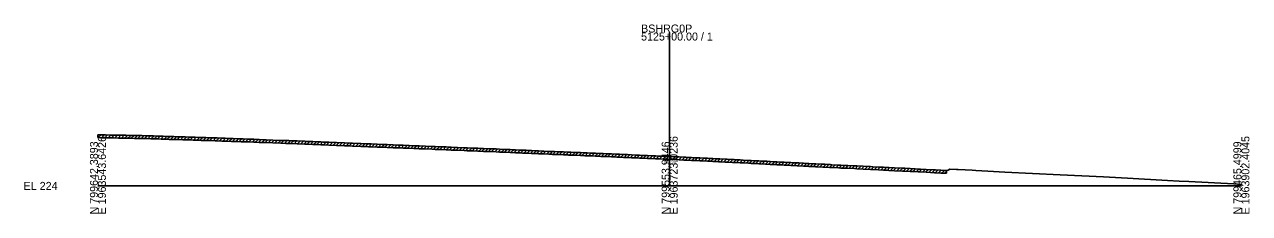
# Model space of a CAD drawing. Extents: x -26 to 1986619, y -10 to 827846.
# Drawn here: x 974.3 to 1402.8, y -9.7 to 56.6 of the extents above; entities that cross this region are included whole.
import ezdxf

# ---------------------------------------------------------------- set-up
doc = ezdxf.new("R2010")
doc.units = 0
for name, color, linetype in [('Default', 7, 'Continuous'), ('RD_GPK_XS_Cell', 7, 'Continuous'), ('RD_XS_ExGround', 7, 'Continuous'), ('RD_XS_ExPaveRet', 7, 'Continuous'), ('RD_XS_TX_Elev_EX', 7, 'Continuous')]:
    doc.layers.add(name, color=color, linetype=linetype)

msp = doc.modelspace()

# ---------------------------------------------------------------- linework, layer by layer
at = {"layer": 'RD_GPK_XS_Cell'}
for p, q in [((1200, 0), (1200, 53.78)), ((1000, 0), (1200, 0)), ((1200, 0), (1400, 0))]:
    msp.add_line(p, q, dxfattribs=at)
at = {"layer": 'RD_XS_ExGround'}
msp.add_lwpolyline([(1000, 17.93), (1000.41, 17.92), (1001.51, 17.89), (1002.28, 17.88), (1002.66, 17.87), (1004.14, 17.84), (1005.44, 17.82), (1007.17, 17.79), (1007.88, 17.77), (1008.23, 17.77), (1009.74, 17.74), (1011.03, 17.71), (1011.61, 17.7), (1012.77, 17.68), (1013.81, 17.65), (1015.34, 17.62), (1016.59, 17.59), (1017.22, 17.57), (1018.49, 17.53), (1019.38, 17.51), (1020.94, 17.46), (1022.17, 17.42), (1022.8, 17.4), (1024.09, 17.36), (1024.96, 17.33), (1026.55, 17.28), (1027.75, 17.25), (1028.41, 17.23), (1029.75, 17.18), (1030.53, 17.16), (1032.14, 17.11), (1033.31, 17.07), (1034, 17.05), (1035.42, 17), (1036.1, 16.98), (1037.74, 16.93), (1038.89, 16.89), (1039.61, 16.87), (1041.05, 16.83), (1041.68, 16.81), (1043.34, 16.74), (1044.47, 16.71), (1045.21, 16.68), (1046.7, 16.63), (1047.26, 16.61), (1048.95, 16.54), (1050.05, 16.51), (1050.82, 16.48), (1052.39, 16.42), (1052.84, 16.41), (1054.55, 16.34), (1055.62, 16.3), (1056.41, 16.27), (1057.99, 16.21), (1058.41, 16.19), (1058.81, 16.18), (1061.19, 16.08), (1063.97, 15.97), (1065.75, 15.91), (1066.77, 15.87), (1067.62, 15.84), (1069.75, 15.76), (1072.34, 15.65), (1073.2, 15.61), (1075.13, 15.54), (1076.95, 15.47), (1077.92, 15.43), (1078.81, 15.39), (1080.82, 15.31), (1083.5, 15.2), (1086.3, 15.1), (1088.15, 15.02), (1089.07, 14.98), (1091.96, 14.87), (1093.76, 14.79), (1094.65, 14.76), (1095.63, 14.72), (1097.63, 14.64), (1099.36, 14.57), (1100.22, 14.53), (1101.22, 14.49), (1103.29, 14.41), (1104.96, 14.34), (1105.8, 14.3), (1106.82, 14.26), (1108.92, 14.18), (1110.56, 14.11), (1111.37, 14.08), (1112.42, 14.03), (1114.56, 13.95), (1116.94, 13.85), (1118.02, 13.8), (1119.88, 13.73), (1120.2, 13.72), (1121.76, 13.65), (1122.52, 13.62), (1123.62, 13.57), (1125.48, 13.5), (1125.82, 13.49), (1128.09, 13.39), (1129.21, 13.35), (1131.07, 13.28), (1131.46, 13.26), (1132.95, 13.2), (1133.67, 13.17), (1134.82, 13.12), (1136.69, 13.05), (1137.16, 13.03), (1139.25, 12.95), (1140.42, 12.89), (1142.29, 12.8), (1142.82, 12.78), (1144.16, 12.73), (1144.82, 12.69), (1146.02, 12.64), (1147.6, 12.57), (1148.47, 12.53), (1149.76, 12.48), (1150.39, 12.45), (1151.62, 12.39), (1153.18, 12.32), (1153.49, 12.31), (1154.13, 12.28), (1155.36, 12.23), (1155.97, 12.2), (1157.76, 12.12), (1158.76, 12.08), (1159.09, 12.06), (1159.77, 12.03), (1160.96, 11.99), (1161.54, 11.96), (1162.83, 11.91), (1164.34, 11.85), (1164.69, 11.83), (1165.43, 11.8), (1166.56, 11.75), (1167.11, 11.73), (1168.76, 11.66), (1169.91, 11.61), (1170.29, 11.59), (1171.09, 11.56), (1172.16, 11.52), (1172.69, 11.5), (1174.04, 11.44), (1175.49, 11.38), (1175.9, 11.36), (1176.76, 11.32), (1177.77, 11.29), (1178.28, 11.27), (1179.64, 11.2), (1181.06, 11.14), (1181.51, 11.12), (1182.43, 11.08), (1183.37, 11.04), (1183.84, 11.02), (1185.24, 10.96), (1186.63, 10.89), (1188.07, 10.83), (1188.97, 10.79), (1189.42, 10.77), (1190.75, 10.71), (1192.21, 10.65), (1193.7, 10.58), (1194.99, 10.52), (1196.26, 10.47), (1197.77, 10.4), (1199.32, 10.33), (1200, 10.3), (1200.56, 10.27), (1201.78, 10.22), (1203.36, 10.14), (1204.96, 10.07), (1205.68, 10.04), (1206.14, 10.01), (1207.62, 9.95), (1208.93, 9.89), (1209.49, 9.86), (1210.6, 9.8), (1211.71, 9.75), (1213.22, 9.69), (1214.51, 9.62), (1215.11, 9.59), (1216.34, 9.53), (1217.09, 9.49), (1217.52, 9.47), (1219.42, 9.38), (1220.07, 9.35), (1221.97, 9.25), (1222.56, 9.22), (1223.02, 9.2), (1224.72, 9.11), (1225.66, 9.06), (1227.59, 8.95), (1228.03, 8.93), (1228.51, 8.9), (1229.99, 8.82), (1231.24, 8.76), (1231.9, 8.73), (1233.49, 8.65), (1233.99, 8.63), (1235.21, 8.55), (1236.79, 8.48), (1237.49, 8.45), (1238.9, 8.38), (1239.46, 8.35), (1240.03, 8.32), (1241.85, 8.22), (1242.38, 8.18), (1243.11, 8.15), (1244.6, 8.09), (1245.15, 8.06), (1246.84, 7.97), (1247.94, 7.91), (1248.71, 7.86), (1250.28, 7.79), (1250.74, 7.76), (1251.19, 7.74), (1253.53, 7.61), (1254.32, 7.57), (1255.92, 7.48), (1256.32, 7.46), (1256.74, 7.44), (1259.1, 7.31), (1259.89, 7.26), (1261.49, 7.2), (1261.9, 7.19), (1262.29, 7.17), (1264.68, 7.05), (1265.51, 7.01), (1267.71, 6.89), (1270.26, 6.76), (1271.12, 6.71), (1273.03, 6.59), (1274.85, 6.53), (1275.82, 6.47), (1276.72, 6.43), (1278.68, 6.33), (1281.4, 6.21), (1282.29, 6.17), (1284.19, 6.08), (1285.93, 6), (1286.97, 5.93), (1287.78, 5.89), (1289.75, 5.79), (1292.64, 5.62), (1292.95, 5.6), (1294.89, 5.5), (1295.91, 5.44), (1296.47, 5.46), (1297.48, 5.47), (1298.02, 5.89), (1300.3, 5.77), (1300.87, 5.74), (1305.77, 5.48), (1307.1, 5.4), (1311.35, 5.17), (1317.29, 4.87), (1336.57, 3.92), (1351.79, 3.16), (1360.16, 2.72), (1374.12, 1.95), (1378.27, 1.7), (1381.62, 1.53), (1397.37, 0.7), (1400, 0.53)], dxfattribs=at)
at = {"layer": 'RD_XS_ExPaveRet'}
for p, q in [((1000, 16.93), (1000, 17.93)), ((1000.1, 16.92), (1001.08, 17.9)), ((1001.25, 16.9), (1002.23, 17.88)), ((1002.41, 16.88), (1003.39, 17.86)), ((1003.56, 16.86), (1004.54, 17.84)), ((1004.72, 16.83), (1005.7, 17.82)), ((1005.88, 16.81), (1006.86, 17.79)), ((1007.03, 16.79), (1008.01, 17.77)), ((1008.19, 16.77), (1009.17, 17.75)), ((1009.34, 16.75), (1010.33, 17.73)), ((1010.5, 16.72), (1011.48, 17.71)), ((1011.66, 16.7), (1012.63, 17.68)), ((1012.81, 16.67), (1013.79, 17.65)), ((1013.96, 16.65), (1014.94, 17.63)), ((1015.11, 16.63), (1016.09, 17.6)), ((1016.26, 16.6), (1017.24, 17.57)), ((1017.41, 16.56), (1018.38, 17.54)), ((1018.55, 16.53), (1019.52, 17.5)), ((1019.7, 16.5), (1020.66, 17.46)), ((1020.84, 16.46), (1021.81, 17.43)), ((1021.98, 16.42), (1022.95, 17.39)), ((1023.12, 16.39), (1024.09, 17.36)), ((1024.27, 16.35), (1025.24, 17.32)), ((1025.41, 16.32), (1026.38, 17.29)), ((1026.55, 16.28), (1027.52, 17.25)), ((1027.69, 16.25), (1028.66, 17.22)), ((1028.84, 16.21), (1029.81, 17.18)), ((1029.98, 16.18), (1030.95, 17.15)), ((1031.12, 16.14), (1032.09, 17.11)), ((1032.27, 16.11), (1033.23, 17.07)), ((1033.4, 16.07), (1034.37, 17.04)), ((1034.55, 16.03), (1035.51, 17)), ((1035.69, 15.99), (1036.66, 16.96)), ((1036.83, 15.96), (1037.8, 16.92)), ((1037.97, 15.92), (1038.94, 16.89)), ((1039.11, 15.89), (1040.08, 16.86)), ((1040.26, 15.85), (1041.23, 16.82)), ((1041.4, 15.81), (1042.36, 16.78)), ((1042.53, 15.77), (1043.5, 16.74)), ((1043.67, 15.73), (1044.64, 16.7)), ((1044.81, 15.7), (1045.78, 16.66)), ((1045.95, 15.66), (1046.92, 16.62)), ((1047.09, 15.62), (1048.05, 16.58)), ((1048.22, 15.57), (1049.19, 16.54)), ((1049.36, 15.53), (1050.33, 16.5)), ((1050.5, 15.49), (1051.46, 16.46)), ((1051.64, 15.45), (1052.6, 16.42)), ((1052.77, 15.41), (1053.73, 16.37)), ((1053.91, 15.36), (1054.87, 16.33)), ((1055.04, 15.32), (1056, 16.28)), ((1056.18, 15.28), (1057.14, 16.24)), ((1057.31, 15.23), (1058.27, 16.2)), ((1058.45, 15.19), (1059.41, 16.15)), ((1059.58, 15.15), (1060.54, 16.11)), ((1060.71, 15.1), (1061.67, 16.06)), ((1061.84, 15.06), (1062.81, 16.02)), ((1062.98, 15.01), (1063.94, 15.98)), ((1064.11, 14.97), (1065.08, 15.93)), ((1065.25, 14.92), (1066.21, 15.89)), ((1066.38, 14.88), (1067.35, 15.85)), ((1067.52, 14.84), (1068.48, 15.8)), ((1068.65, 14.8), (1069.62, 15.76)), ((1069.79, 14.75), (1070.75, 15.71)), ((1070.92, 14.71), (1071.88, 15.67)), ((1072.05, 14.66), (1073.01, 15.62)), ((1073.18, 14.62), (1074.15, 15.58)), ((1074.32, 14.57), (1075.28, 15.54)), ((1075.45, 14.53), (1076.41, 15.49)), ((1076.58, 14.48), (1077.54, 15.44)), ((1077.72, 14.44), (1078.68, 15.4)), ((1078.85, 14.39), (1079.81, 15.35)), ((1079.98, 14.35), (1080.94, 15.31)), ((1081.12, 14.3), (1082.08, 15.26)), ((1082.25, 14.26), (1083.21, 15.22)), ((1083.38, 14.21), (1084.34, 15.17)), ((1084.51, 14.16), (1085.48, 15.13)), ((1085.65, 14.12), (1086.61, 15.08)), ((1086.78, 14.08), (1087.74, 15.04)), ((1087.91, 14.03), (1088.87, 14.99)), ((1089.04, 13.98), (1090, 14.94)), ((1090.18, 13.94), (1091.14, 14.9)), ((1091.31, 13.89), (1092.27, 14.85)), ((1092.44, 13.85), (1093.4, 14.81)), ((1093.57, 13.8), (1094.53, 14.76)), ((1094.71, 13.76), (1095.67, 14.72)), ((1095.84, 13.71), (1096.8, 14.67)), ((1096.97, 13.67), (1097.94, 14.63)), ((1098.11, 13.62), (1099.06, 14.58)), ((1099.24, 13.57), (1100.2, 14.53)), ((1100.37, 13.53), (1101.33, 14.48)), ((1101.5, 13.48), (1102.46, 14.44)), ((1102.63, 13.44), (1103.59, 14.4)), ((1103.76, 13.39), (1104.72, 14.35)), ((1104.89, 13.34), (1105.85, 14.3)), ((1106.02, 13.29), (1106.98, 14.25)), ((1107.16, 13.25), (1108.12, 14.21)), ((1108.29, 13.2), (1109.25, 14.16)), ((1109.42, 13.16), (1110.38, 14.12)), ((1110.55, 13.11), (1111.51, 14.07)), ((1111.68, 13.06), (1112.64, 14.02)), ((1112.81, 13.01), (1113.78, 13.98)), ((1113.95, 12.97), (1114.91, 13.93)), ((1115.08, 12.93), (1116.04, 13.89)), ((1116.21, 12.88), (1117.17, 13.84)), ((1117.34, 12.83), (1118.3, 13.79)), ((1118.47, 12.78), (1119.44, 13.75)), ((1119.61, 12.74), (1120.57, 13.7)), ((1120.74, 12.69), (1121.7, 13.65)), ((1121.87, 12.65), (1122.83, 13.61)), ((1123, 12.6), (1123.96, 13.56)), ((1124.13, 12.55), (1125.1, 13.52)), ((1125.27, 12.51), (1126.23, 13.47)), ((1126.4, 12.47), (1127.36, 13.42)), ((1127.53, 12.42), (1128.49, 13.38)), ((1128.66, 12.37), (1129.62, 13.33)), ((1129.79, 12.32), (1130.76, 13.29)), ((1130.93, 12.28), (1131.89, 13.24)), ((1132.06, 12.24), (1133.02, 13.2)), ((1133.2, 12.19), (1134.15, 13.15)), ((1134.32, 12.14), (1135.29, 13.1)), ((1135.46, 12.1), (1136.42, 13.06)), ((1136.59, 12.05), (1137.56, 13.02)), ((1137.73, 12.01), (1138.69, 12.97)), ((1138.86, 11.97), (1139.82, 12.92)), ((1139.99, 11.91), (1140.94, 12.87)), ((1141.11, 11.86), (1142.06, 12.81)), ((1142.23, 11.8), (1143.19, 12.76)), ((1143.36, 11.76), (1144.32, 12.72)), ((1144.49, 11.71), (1145.45, 12.67)), ((1145.62, 11.66), (1146.58, 12.61)), ((1146.75, 11.61), (1147.7, 12.56)), ((1147.87, 11.55), (1148.83, 12.51)), ((1149, 11.51), (1149.96, 12.47)), ((1150.13, 11.46), (1151.09, 12.42)), ((1151.26, 11.41), (1152.22, 12.37)), ((1152.39, 11.36), (1153.34, 12.31)), ((1153.51, 11.31), (1154.47, 12.26)), ((1154.64, 11.26), (1155.6, 12.22)), ((1155.77, 11.21), (1156.73, 12.17)), ((1156.9, 11.16), (1157.86, 12.12)), ((1158.03, 11.11), (1158.99, 12.07)), ((1159.16, 11.06), (1160.12, 12.02)), ((1160.29, 11.01), (1161.25, 11.97)), ((1161.42, 10.97), (1162.38, 11.93)), ((1162.55, 10.92), (1163.51, 11.88)), ((1163.68, 10.87), (1164.64, 11.83)), ((1164.82, 10.83), (1165.77, 11.78)), ((1165.94, 10.78), (1166.9, 11.74)), ((1167.07, 10.73), (1168.03, 11.69)), ((1168.2, 10.68), (1169.16, 11.64)), ((1169.33, 10.63), (1170.29, 11.59)), ((1170.46, 10.58), (1171.43, 11.55)), ((1171.6, 10.54), (1172.56, 11.5)), ((1172.73, 10.5), (1173.69, 11.45)), ((1173.86, 10.45), (1174.82, 11.4)), ((1174.99, 10.4), (1175.95, 11.35)), ((1176.12, 10.35), (1177.08, 11.31)), ((1177.25, 10.31), (1178.22, 11.27)), ((1178.39, 10.26), (1179.34, 11.22)), ((1179.51, 10.21), (1180.47, 11.16)), ((1180.64, 10.16), (1181.59, 11.11)), ((1181.76, 10.1), (1182.73, 11.06)), ((1182.9, 10.06), (1183.86, 11.02)), ((1184.03, 10.01), (1184.99, 10.97)), ((1185.16, 9.96), (1186.11, 10.92)), ((1186.28, 9.91), (1187.24, 10.87)), ((1187.41, 9.86), (1188.37, 10.82)), ((1188.54, 9.81), (1189.5, 10.77)), ((1189.67, 9.76), (1190.62, 10.72)), ((1190.79, 9.71), (1191.75, 10.67)), ((1191.92, 9.66), (1192.88, 10.62)), ((1193.05, 9.61), (1194.01, 10.57)), ((1194.18, 9.56), (1195.14, 10.52)), ((1195.31, 9.51), (1196.26, 10.47)), ((1196.43, 9.46), (1197.39, 10.42)), ((1197.56, 9.41), (1198.52, 10.37)), ((1198.69, 9.36), (1199.64, 10.31)), ((1199.81, 9.31), (1200.77, 10.26)), ((1200.94, 9.25), (1201.9, 10.21)), ((1202.07, 9.2), (1203.02, 10.16)), ((1203.19, 9.15), (1204.15, 10.11)), ((1204.32, 9.1), (1205.28, 10.05)), ((1205.45, 9.05), (1206.4, 10)), ((1206.57, 9), (1207.53, 9.95)), ((1207.7, 8.95), (1208.66, 9.9)), ((1208.83, 8.89), (1209.78, 9.85)), ((1209.95, 8.84), (1210.9, 9.79)), ((1211.07, 8.78), (1212.03, 9.74)), ((1212.2, 8.73), (1213.16, 9.69)), ((1213.33, 8.68), (1214.28, 9.63)), ((1214.45, 8.63), (1215.4, 9.58)), ((1215.57, 8.57), (1216.52, 9.52)), ((1216.69, 8.51), (1217.64, 9.46)), ((1217.81, 8.45), (1218.77, 9.41)), ((1218.94, 8.4), (1219.89, 9.35)), ((1220.06, 8.35), (1221.01, 9.3)), ((1221.18, 8.29), (1222.13, 9.24)), ((1222.3, 8.23), (1223.25, 9.18)), ((1223.42, 8.17), (1224.37, 9.12)), ((1224.54, 8.12), (1225.49, 9.07)), ((1225.66, 8.06), (1226.61, 9.01)), ((1226.78, 8), (1227.73, 8.94)), ((1227.89, 7.93), (1228.84, 8.88)), ((1229.01, 7.87), (1229.96, 8.82)), ((1230.13, 7.81), (1231.08, 8.77)), ((1231.25, 7.76), (1232.21, 8.71)), ((1232.38, 7.7), (1233.33, 8.66)), ((1233.5, 7.65), (1234.45, 8.6)), ((1234.62, 7.59), (1235.56, 8.54)), ((1235.73, 7.53), (1236.69, 8.48)), ((1236.86, 7.48), (1237.81, 8.43)), ((1237.98, 7.42), (1238.94, 8.38)), ((1239.11, 7.37), (1240.06, 8.32)), ((1240.23, 7.31), (1241.17, 8.25)), ((1241.34, 7.25), (1242.29, 8.19)), ((1242.45, 7.18), (1243.41, 8.13)), ((1243.58, 7.13), (1244.54, 8.09)), ((1244.71, 7.08), (1245.66, 8.03)), ((1245.83, 7.02), (1246.78, 7.97)), ((1246.95, 6.96), (1247.9, 7.91)), ((1248.06, 6.9), (1249.01, 7.85)), ((1249.18, 6.84), (1250.14, 7.79)), ((1250.31, 6.79), (1251.26, 7.74)), ((1251.42, 6.73), (1252.37, 7.67)), ((1252.54, 6.66), (1253.49, 7.61)), ((1253.66, 6.6), (1254.61, 7.55)), ((1254.78, 6.54), (1255.73, 7.49)), ((1255.9, 6.49), (1256.84, 7.43)), ((1257.01, 6.42), (1257.96, 7.37)), ((1258.13, 6.36), (1259.07, 7.31)), ((1259.24, 6.3), (1260.19, 7.25)), ((1260.37, 6.24), (1261.33, 7.21)), ((1261.5, 6.2), (1262.46, 7.16)), ((1262.63, 6.15), (1263.58, 7.11)), ((1263.75, 6.1), (1264.71, 7.05)), ((1264.88, 6.04), (1265.83, 6.99)), ((1266, 5.98), (1266.95, 6.93)), ((1267.12, 5.92), (1268.06, 6.87)), ((1268.23, 5.86), (1269.18, 6.81)), ((1269.35, 5.81), (1270.3, 6.76)), ((1270.47, 5.75), (1271.42, 6.69)), ((1271.58, 5.68), (1272.53, 6.62)), ((1272.7, 5.61), (1273.65, 6.57)), ((1273.82, 5.56), (1274.79, 6.53)), ((1274.96, 5.52), (1275.91, 6.47)), ((1276.08, 5.46), (1277.03, 6.41)), ((1277.2, 5.41), (1278.15, 6.36)), ((1278.32, 5.35), (1279.28, 6.31)), ((1279.45, 5.3), (1280.4, 6.25)), ((1280.57, 5.25), (1281.53, 6.2)), ((1281.7, 5.2), (1282.66, 6.15)), ((1282.83, 5.14), (1283.78, 6.1)), ((1283.95, 5.09), (1284.91, 6.04)), ((1285.08, 5.04), (1286.03, 5.99)), ((1286.2, 4.98), (1287.14, 5.92)), ((1287.31, 4.91), (1288.26, 5.86)), ((1288.43, 4.86), (1289.38, 5.81)), ((1289.55, 4.8), (1290.5, 5.74)), ((1290.66, 4.73), (1291.61, 5.68)), ((1291.78, 4.67), (1292.72, 5.62)), ((1292.89, 4.61), (1293.84, 5.55)), ((1294.01, 4.54), (1294.96, 5.49)), ((1295.12, 4.48), (1296.09, 5.44)), ((1296.27, 4.45), (1296.82, 5)), ((1296.82, 4.47), (1296.82, 5.47))]:
    msp.add_line(p, q, dxfattribs=at)
msp.add_lwpolyline([(1000, 16.93), (1000.41, 16.92), (1001.51, 16.89), (1002.28, 16.88), (1002.66, 16.87), (1004.14, 16.84), (1005.44, 16.82), (1007.17, 16.79), (1007.88, 16.77), (1008.23, 16.77), (1009.74, 16.74), (1011.03, 16.71), (1011.61, 16.7), (1012.77, 16.68), (1013.81, 16.65), (1015.34, 16.62), (1016.59, 16.59), (1017.22, 16.57), (1018.49, 16.53), (1019.38, 16.51), (1020.94, 16.46), (1022.17, 16.42), (1022.8, 16.4), (1024.09, 16.36), (1024.96, 16.33), (1026.55, 16.28), (1027.75, 16.25), (1028.41, 16.23), (1029.75, 16.18), (1030.53, 16.16), (1032.14, 16.11), (1033.31, 16.07), (1034, 16.05), (1035.42, 16), (1036.1, 15.98), (1037.74, 15.93), (1038.89, 15.89), (1039.61, 15.87), (1041.05, 15.83), (1041.68, 15.81), (1043.34, 15.74), (1044.47, 15.71), (1045.21, 15.68), (1046.7, 15.63), (1047.26, 15.61), (1048.95, 15.54), (1050.05, 15.51), (1050.82, 15.48), (1052.39, 15.42), (1052.84, 15.41), (1054.55, 15.34), (1055.62, 15.3), (1056.41, 15.27), (1057.99, 15.21), (1058.41, 15.19), (1058.81, 15.18), (1061.19, 15.08), (1063.97, 14.97), (1065.75, 14.91), (1066.77, 14.87), (1067.62, 14.84), (1069.75, 14.76), (1072.34, 14.65), (1073.2, 14.61), (1075.13, 14.54), (1076.95, 14.47), (1077.92, 14.43), (1078.81, 14.39), (1080.82, 14.31), (1083.5, 14.2), (1086.3, 14.1), (1088.15, 14.02), (1089.07, 13.98), (1091.96, 13.87), (1093.76, 13.79), (1094.65, 13.76), (1095.63, 13.72), (1097.63, 13.64), (1099.36, 13.57), (1100.22, 13.53), (1101.22, 13.49), (1103.29, 13.41), (1104.96, 13.34), (1105.8, 13.3), (1106.82, 13.26), (1108.92, 13.18), (1110.56, 13.11), (1111.37, 13.08), (1112.42, 13.03), (1114.56, 12.95), (1116.94, 12.85), (1118.02, 12.8), (1119.88, 12.73), (1120.2, 12.72), (1121.76, 12.65), (1122.52, 12.62), (1123.62, 12.57), (1125.48, 12.5), (1125.82, 12.49), (1128.09, 12.39), (1129.21, 12.35), (1131.07, 12.28), (1131.46, 12.26), (1132.95, 12.2), (1133.67, 12.17), (1134.82, 12.12), (1136.69, 12.05), (1137.16, 12.03), (1139.25, 11.95), (1140.42, 11.89), (1142.29, 11.8), (1142.82, 11.78), (1144.16, 11.73), (1144.82, 11.69), (1146.02, 11.64), (1147.6, 11.57), (1148.47, 11.53), (1149.76, 11.48), (1150.39, 11.45), (1151.62, 11.39), (1153.18, 11.32), (1153.49, 11.31), (1154.13, 11.28), (1155.36, 11.23), (1155.97, 11.2), (1157.76, 11.12), (1158.76, 11.08), (1159.09, 11.06), (1159.77, 11.03), (1160.96, 10.99), (1161.54, 10.96), (1162.83, 10.91), (1164.34, 10.85), (1164.69, 10.83), (1165.43, 10.8), (1166.56, 10.75), (1167.11, 10.73), (1168.76, 10.66), (1169.91, 10.61), (1170.29, 10.59), (1171.09, 10.56), (1172.16, 10.52), (1172.69, 10.5), (1174.04, 10.44), (1175.49, 10.38), (1175.9, 10.36), (1176.76, 10.32), (1177.77, 10.29), (1178.28, 10.27), (1179.64, 10.2), (1181.06, 10.14), (1181.51, 10.12), (1182.43, 10.08), (1183.37, 10.04), (1183.84, 10.02), (1185.24, 9.96), (1186.63, 9.89), (1188.07, 9.83), (1188.97, 9.79), (1189.42, 9.77), (1190.75, 9.71), (1192.21, 9.65), (1193.7, 9.58), (1194.99, 9.52), (1196.26, 9.47), (1197.77, 9.4), (1199.32, 9.33), (1200, 9.3), (1200.56, 9.27), (1201.78, 9.22), (1203.36, 9.14), (1204.96, 9.07), (1205.68, 9.04), (1206.14, 9.01), (1207.62, 8.95), (1208.93, 8.89), (1209.49, 8.86), (1210.6, 8.8), (1211.71, 8.75), (1213.22, 8.69), (1214.51, 8.62), (1215.11, 8.59), (1216.34, 8.53), (1217.09, 8.49), (1217.52, 8.47), (1219.42, 8.38), (1220.07, 8.35), (1221.97, 8.25), (1222.56, 8.22), (1223.02, 8.2), (1224.72, 8.11), (1225.66, 8.06), (1227.59, 7.95), (1228.03, 7.93), (1228.51, 7.9), (1229.99, 7.82), (1231.24, 7.76), (1231.9, 7.73), (1233.49, 7.65), (1233.99, 7.63), (1235.21, 7.55), (1236.79, 7.48), (1237.49, 7.45), (1238.9, 7.38), (1239.46, 7.35), (1240.03, 7.32), (1241.85, 7.22), (1242.38, 7.18), (1243.11, 7.15), (1244.6, 7.09), (1245.15, 7.06), (1246.84, 6.97), (1247.94, 6.91), (1248.71, 6.86), (1250.28, 6.79), (1250.74, 6.76), (1251.19, 6.74), (1253.53, 6.61), (1254.32, 6.57), (1255.92, 6.48), (1256.32, 6.46), (1256.74, 6.44), (1259.1, 6.31), (1259.89, 6.26), (1261.49, 6.2), (1261.9, 6.19), (1262.29, 6.17), (1264.68, 6.05), (1265.51, 6.01), (1267.71, 5.89), (1270.26, 5.76), (1271.12, 5.71), (1273.03, 5.59), (1274.85, 5.53), (1275.82, 5.47), (1276.72, 5.43), (1278.68, 5.33), (1281.4, 5.21), (1282.29, 5.17), (1284.19, 5.08), (1285.93, 5), (1286.97, 4.93), (1287.78, 4.89), (1289.75, 4.79), (1292.64, 4.62), (1292.95, 4.6), (1294.89, 4.5), (1295.91, 4.44), (1296.47, 4.46), (1296.82, 4.47)], dxfattribs=at)

# ---------------------------------------------------------------- texts
at = {"layer": 'Default'}
msp.add_text('-', height=0.0001, dxfattribs=at).set_placement((1000, 0))
at = {"layer": 'RD_GPK_XS_Cell'}
for s, p in [('BSHRG0P', (1190, 53.78)), ('5125+00.00 / 1', (1190, 50.98)), ('EL 224', (974, -1.4))]:
    msp.add_text(s, height=2.8, dxfattribs=at).set_placement(p)
for s, p in [('E 1963543.6426', (1002.8, -10)), ('E 1963723.0236', (1202.8, -10)), ('E 1963902.4045', (1402.8, -10)), ('N 799642.3893', (1000, -10)), ('N 799553.9446', (1200, -10)), ('N 799465.4999', (1400, -10))]:
    msp.add_text(s, height=2.8, rotation=90, dxfattribs=at).set_placement(p)
at = {"layer": 'RD_XS_TX_Elev_EX'}
msp.add_text('234.30', height=1, dxfattribs=at).set_placement((1197.95, 7.8))

doc.saveas('drawing.dxf')
